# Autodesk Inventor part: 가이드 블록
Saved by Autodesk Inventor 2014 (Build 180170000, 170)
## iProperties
Created: 2026-09
Part Number: 가이드 블록
Material: 강철, 주조
Document SubType Name: Modeling
Designer: dg
Density: 7.85 g/cm^3
Appearance: 강철 - 주조
Mass: 128.923 g
Surface Area: 75.2607 cm^2
Volume: 16.4233 cm^3
Author: jhkim
Creation Date: 2026-08-26
Sending System: Autodesk Inventor 2027
Preprocessor: ST-DEVELOPER v20.1
Author: dg
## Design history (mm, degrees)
node "가이드 블록1"
node "솔리드1"
node "기준1"
